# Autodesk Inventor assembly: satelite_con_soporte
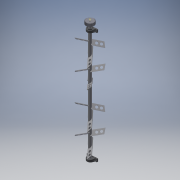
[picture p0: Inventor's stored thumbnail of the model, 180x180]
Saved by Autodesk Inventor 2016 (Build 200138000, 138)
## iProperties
Created: 2016-10
Part Number: satelite_con_soporte
Document SubType Name: Assembly
Designer: Ingenieria
Author: Ingenieria
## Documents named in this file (3)
- C:\Users\ingenieria\Desktop\INGENIERIA\Proyectos\2016\Enfriador_4\Planos\satelite_con_soporte.iam
- C:\Users\ingenieria\Desktop\INGENIERIA\Proyectos\2016\Enfriador_4\Planos\Montaje_satelites.iam
- C:\Users\ingenieria\Desktop\INGENIERIA\Proyectos\2016\Enfriador_4\Planos\SY 55 FM.iam
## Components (3 placed, 2 different names)
1. Montaje_satelites:1 [sub-assembly] — Mate:1, Mate:2, Mate:5, Mate:7
2. SY 55 FM:1 [sub-assembly] — Mate:3, Angle:1, Mate:5
3. SY 55 FM:2 [sub-assembly] — Mate:4, Mate:6, Mate:7
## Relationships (8: Mate 7, Angle 1)
- Mate:1: Montaje_satelites:1
- Mate:2: Montaje_satelites:1
- Mate:3: SY 55 FM:1
- Mate:4: SY 55 FM:2
- Angle:1: SY 55 FM:1
- Mate:5: Montaje_satelites:1 ↔ SY 55 FM:1
- Mate:6: SY 55 FM:2
- Mate:7: Montaje_satelites:1 ↔ SY 55 FM:2
